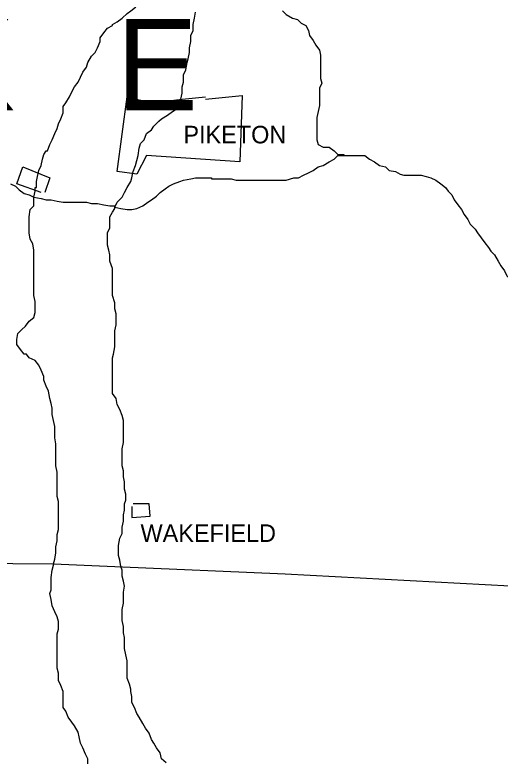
# Model space of a CAD drawing. Extents: x 0 to 34, y 0 to 22.
# Drawn here: x 5.85 to 6.39, y 17.259 to 18.089 of the extents above; entities that cross this region are included whole.
import ezdxf

# ---------------------------------------------------------------- set-up
doc = ezdxf.new("R2010")
doc.units = 0
doc.layers.add('Default', color=7, linetype='Continuous')
doc.layers.add('TR_Turning_Path1', color=7, linetype='Continuous')

msp = doc.modelspace()

# ---------------------------------------------------------------- linework, layer by layer
at = {"layer": 'Default'}
for points in [[(5.95854, 18.07894), (5.96399, 18.08167), (5.96944, 18.08576), (5.9749, 18.09121), (5.97899, 18.09394), (5.98444, 18.09803), (5.98717, 18.10212), (5.98853, 18.10894), (5.99262, 18.11575), (5.99399, 18.11712)], [(6.04443, 18.05304), (6.0458, 18.05985), (6.0458, 18.06667), (6.04852, 18.07212), (6.04852, 18.07894), (6.04989, 18.08576), (6.05125, 18.09257)], [(6.14805, 18.09394), (6.15214, 18.08985), (6.15896, 18.08576), (6.16441, 18.08439), (6.1685, 18.0803), (6.17396, 18.07758), (6.17668, 18.07212), (6.17805, 18.06667), (6.18214, 18.06122), (6.18487, 18.05576), (6.18896, 18.05031), (6.19032, 18.04486), (6.19032, 18.03804), (6.19032, 18.03122), (6.19032, 18.02577), (6.19032, 18.01895), (6.19168, 18.0135)], [(5.88628, 17.93851), (5.889, 17.94533), (5.89173, 17.95078), (5.89446, 17.9576), (5.89718, 17.96305), (5.89855, 17.9685), (5.90127, 17.97396), (5.904, 17.98077), (5.904, 17.98759), (5.90673, 17.99168), (5.91082, 17.9985), (5.91354, 18.00395), (5.91627, 18.00941), (5.92036, 18.01486), (5.92309, 18.02031), (5.92582, 18.02577), (5.92991, 18.03122), (5.93127, 18.03667), (5.93536, 18.04349), (5.93945, 18.04758), (5.94218, 18.05304), (5.9449, 18.05985), (5.9449, 18.06394), (5.94899, 18.0694), (5.95308, 18.07485), (5.95854, 18.07758), (5.95854, 18.07894)], [(5.96126, 17.87579), (5.96399, 17.88124), (5.96944, 17.8867), (5.97217, 17.89215), (5.9749, 17.89761), (5.97899, 17.90442), (5.98035, 17.90851), (5.98172, 17.91533), (5.98444, 17.92215), (5.98581, 17.9276), (5.98717, 17.93305), (5.98853, 17.94124), (5.9899, 17.94669), (5.99399, 17.95078), (5.99671, 17.9576), (6.00217, 17.96169), (6.00489, 17.96578), (6.01035, 17.97123), (6.01307, 17.97396), (6.01989, 17.97805), (6.02534, 17.98214), (6.02944, 17.98486), (6.03353, 17.99032), (6.03489, 17.99577), (6.03625, 18.00259), (6.03625, 18.00941), (6.03762, 18.01486), (6.03762, 18.02304), (6.04034, 18.02849), (6.04171, 18.03667), (6.04307, 18.04076), (6.04443, 18.04758), (6.04443, 18.05167), (6.04443, 18.05304)], [(6.19168, 18.0135), (6.18896, 18.00804), (6.18896, 18.00259), (6.18896, 17.99577), (6.18896, 17.98895), (6.18759, 17.98214), (6.18623, 17.97532), (6.18623, 17.96987), (6.18623, 17.96305), (6.18623, 17.9576), (6.18623, 17.95078), (6.18759, 17.94533), (6.19305, 17.9426), (6.19986, 17.9426), (6.20532, 17.93851), (6.20941, 17.93442), (6.21622, 17.93442), (6.21622, 17.93305)], [(6.06216, 17.99577), (6.10306, 17.99986), (6.10033, 17.92624), (5.99671, 17.93305), (5.98581, 17.9126), (5.96399, 17.91533), (5.9749, 17.9985), (6.00217, 17.99168), (6.03625, 17.99577), (6.06216, 17.9985)], [(5.87401, 17.89761), (5.87401, 17.90442), (5.87537, 17.90988), (5.87673, 17.91669), (5.87946, 17.92215), (5.88082, 17.92896), (5.88219, 17.93442), (5.88491, 17.93851), (5.88628, 17.93851)], [(6.06897, 17.90715), (6.07579, 17.90715), (6.08397, 17.90715), (6.09079, 17.90715), (6.09624, 17.90579), (6.10306, 17.90579), (6.10988, 17.90579), (6.11669, 17.90579), (6.12215, 17.90579), (6.1276, 17.90579), (6.13578, 17.90579), (6.14124, 17.90579), (6.14805, 17.90579), (6.15214, 17.90579), (6.16032, 17.90851), (6.16578, 17.90851), (6.17123, 17.91124), (6.17668, 17.91397), (6.18214, 17.91669), (6.18759, 17.92078), (6.19305, 17.92215), (6.19986, 17.92624), (6.20532, 17.92896), (6.20941, 17.93305), (6.21486, 17.93305), (6.21622, 17.93305)], [(6.06897, 17.90715), (6.07579, 17.90715), (6.08397, 17.90715), (6.09079, 17.90715), (6.09624, 17.90579), (6.10306, 17.90579), (6.10988, 17.90579), (6.11669, 17.90579), (6.12215, 17.90579), (6.1276, 17.90579), (6.13578, 17.90579), (6.14124, 17.90579), (6.14805, 17.90579), (6.15214, 17.90579), (6.16032, 17.90851), (6.16578, 17.90851), (6.17123, 17.91124), (6.17668, 17.91397), (6.18214, 17.91669), (6.18759, 17.92078), (6.19305, 17.92215), (6.19986, 17.92624), (6.20532, 17.92896), (6.20941, 17.93305), (6.21486, 17.93305), (6.21622, 17.93305)], [(6.21622, 17.93305), (6.22304, 17.93305), (6.22849, 17.93305), (6.23395, 17.93305), (6.2394, 17.93305), (6.24486, 17.92896), (6.25031, 17.92624), (6.25576, 17.92215), (6.26258, 17.92078), (6.26667, 17.91669), (6.27349, 17.91533), (6.27894, 17.9126), (6.28303, 17.91124), (6.28985, 17.91124), (6.29667, 17.91124), (6.30212, 17.91124), (6.30757, 17.90988), (6.31303, 17.90851), (6.31848, 17.90579), (6.31848, 17.90579)], [(6.21622, 17.93305), (6.22304, 17.93305), (6.22849, 17.93305), (6.23395, 17.93305), (6.2394, 17.93305), (6.24486, 17.92896), (6.25031, 17.92624), (6.25576, 17.92215), (6.26258, 17.92078), (6.26667, 17.91669), (6.27349, 17.91533), (6.27894, 17.9126), (6.28303, 17.91124), (6.28985, 17.91124), (6.29667, 17.91124), (6.30212, 17.91124), (6.30757, 17.90988), (6.31303, 17.90851), (6.31848, 17.90579), (6.31848, 17.90579)], [(5.87946, 17.89215), (5.85219, 17.9017), (5.85901, 17.92078), (5.889, 17.90851), (5.88355, 17.89215)], [(5.96126, 17.87579), (5.96808, 17.87443), (5.9749, 17.87306), (5.98035, 17.87306), (5.98581, 17.87443), (5.99262, 17.87715), (5.99808, 17.88124), (6.00217, 17.88397), (6.00762, 17.88806), (6.01171, 17.89215), (6.01716, 17.89624), (6.02125, 17.89897), (6.02671, 17.9017), (6.03353, 17.90442), (6.03762, 17.90579), (6.0458, 17.90715), (6.05125, 17.90851), (6.05807, 17.90851), (6.06352, 17.90851), (6.06897, 17.90851), (6.06897, 17.90715)], [(5.96126, 17.87579), (5.96808, 17.87443), (5.9749, 17.87306), (5.98035, 17.87306), (5.98581, 17.87443), (5.99262, 17.87715), (5.99808, 17.88124), (6.00217, 17.88397), (6.00762, 17.88806), (6.01171, 17.89215), (6.01716, 17.89624), (6.02125, 17.89897), (6.02671, 17.9017), (6.03353, 17.90442), (6.03762, 17.90579), (6.0458, 17.90715), (6.05125, 17.90851), (6.05807, 17.90851), (6.06352, 17.90851), (6.06897, 17.90851), (6.06897, 17.90715)], [(5.84537, 17.9017), (5.85083, 17.89897), (5.85492, 17.89488), (5.86037, 17.89079), (5.86582, 17.88943), (5.87128, 17.8867), (5.87128, 17.8867), (5.87128, 17.8867)], [(5.84537, 17.9017), (5.85083, 17.89897), (5.85492, 17.89488), (5.86037, 17.89079), (5.86582, 17.88943), (5.87128, 17.8867), (5.87128, 17.8867), (5.87128, 17.8867)], [(6.31848, 17.90579), (6.32393, 17.9017), (6.32939, 17.89761), (6.33211, 17.89352), (6.3362, 17.88943), (6.33893, 17.88397), (6.34302, 17.87852), (6.34711, 17.87306), (6.34984, 17.86761), (6.35393, 17.86216), (6.35666, 17.8567), (6.36211, 17.85125), (6.36484, 17.84716), (6.36893, 17.84171), (6.37302, 17.83625), (6.37711, 17.8308), (6.37983, 17.82671), (6.38392, 17.82262), (6.38392, 17.82262)], [(6.31848, 17.90579), (6.32393, 17.9017), (6.32939, 17.89761), (6.33211, 17.89352), (6.3362, 17.88943), (6.33893, 17.88397), (6.34302, 17.87852), (6.34711, 17.87306), (6.34984, 17.86761), (6.35393, 17.86216), (6.35666, 17.8567), (6.36211, 17.85125), (6.36484, 17.84716), (6.36893, 17.84171), (6.37302, 17.83625), (6.37711, 17.8308), (6.37983, 17.82671), (6.38392, 17.82262), (6.38392, 17.82262)], [(5.87128, 17.8867), (5.87264, 17.89352), (5.87264, 17.89761), (5.87401, 17.89761)], [(5.86037, 17.71218), (5.85628, 17.71763), (5.85219, 17.72309), (5.85219, 17.72854), (5.85355, 17.73536), (5.85764, 17.73945), (5.86173, 17.74354), (5.86582, 17.74899), (5.87128, 17.75308), (5.87264, 17.75854), (5.87264, 17.76399), (5.87264, 17.77081), (5.87128, 17.77762), (5.87128, 17.78444), (5.87128, 17.79126), (5.87128, 17.79671), (5.87128, 17.80353), (5.87128, 17.80898), (5.87128, 17.8158), (5.87128, 17.82262), (5.87128, 17.82807), (5.86991, 17.83489), (5.86719, 17.84034), (5.86582, 17.84716), (5.86582, 17.85261), (5.86582, 17.85943), (5.86582, 17.86488), (5.86719, 17.87306), (5.87128, 17.87715), (5.87128, 17.88397), (5.87128, 17.88533), (5.87128, 17.8867)], [(5.87128, 17.8867), (5.87946, 17.88533), (5.88491, 17.88397), (5.89037, 17.88397), (5.89718, 17.88261), (5.904, 17.88124), (5.90945, 17.88124), (5.91627, 17.88124), (5.92309, 17.88124), (5.92991, 17.88124), (5.93536, 17.87988), (5.94218, 17.87988), (5.94899, 17.87852), (5.95581, 17.87715), (5.96126, 17.87715), (5.96126, 17.87579)], [(5.87128, 17.8867), (5.87946, 17.88533), (5.88491, 17.88397), (5.89037, 17.88397), (5.89718, 17.88261), (5.904, 17.88124), (5.90945, 17.88124), (5.91627, 17.88124), (5.92309, 17.88124), (5.92991, 17.88124), (5.93536, 17.87988), (5.94218, 17.87988), (5.94899, 17.87852), (5.95581, 17.87715), (5.96126, 17.87715), (5.96126, 17.87579)], [(5.96126, 17.73263), (5.96126, 17.73809), (5.96263, 17.7449), (5.96263, 17.75172), (5.96263, 17.75717), (5.96126, 17.76263), (5.96126, 17.76944), (5.95854, 17.77762), (5.95854, 17.78308), (5.95854, 17.7899), (5.95854, 17.79535), (5.95854, 17.80217), (5.95854, 17.80762), (5.95581, 17.8158), (5.95581, 17.82262), (5.95445, 17.82807), (5.95308, 17.83352), (5.95308, 17.84034), (5.95308, 17.84716), (5.95581, 17.85261), (5.95581, 17.85943), (5.95581, 17.86488), (5.95854, 17.87034), (5.96126, 17.87443), (5.96126, 17.87579)], [(6.38392, 17.82262), (6.38801, 17.8158), (6.39074, 17.81035), (6.39483, 17.80489), (6.39756, 17.79944), (6.40301, 17.79399), (6.40574, 17.7899), (6.40983, 17.78581), (6.41392, 17.77899), (6.41801, 17.7749), (6.4221, 17.76944), (6.42892, 17.76672), (6.43437, 17.76399), (6.43982, 17.76263), (6.44664, 17.76126), (6.4521, 17.76126), (6.45891, 17.7599), (6.46573, 17.75854), (6.47118, 17.75854), (6.478, 17.75854), (6.47936, 17.75854)], [(6.38392, 17.82262), (6.38801, 17.8158), (6.39074, 17.81035), (6.39483, 17.80489), (6.39756, 17.79944), (6.40301, 17.79399), (6.40574, 17.7899), (6.40983, 17.78581), (6.41392, 17.77899), (6.41801, 17.7749), (6.4221, 17.76944), (6.42892, 17.76672), (6.43437, 17.76399), (6.43982, 17.76263), (6.44664, 17.76126), (6.4521, 17.76126), (6.45891, 17.7599), (6.46573, 17.75854), (6.47118, 17.75854), (6.478, 17.75854), (6.47936, 17.75854)], [(5.96808, 17.47631), (5.96672, 17.48313), (5.96535, 17.48858), (5.96535, 17.4954), (5.96535, 17.49949), (5.96672, 17.50767), (5.96944, 17.51312), (5.96944, 17.51994), (5.97081, 17.52676), (5.97081, 17.53357), (5.97217, 17.53903), (5.97217, 17.54584), (5.97353, 17.54993), (5.97353, 17.55675), (5.97217, 17.5622), (5.97217, 17.57038), (5.97081, 17.57584), (5.97081, 17.58266), (5.96944, 17.58811), (5.96944, 17.59493), (5.96944, 17.60174), (5.96944, 17.6072), (5.97081, 17.61401), (5.97081, 17.61947), (5.97081, 17.62628), (5.97081, 17.63174), (5.97081, 17.63856), (5.96944, 17.64401), (5.96672, 17.65083), (5.96399, 17.65628), (5.96263, 17.6631), (5.95854, 17.66855), (5.95854, 17.67537), (5.95854, 17.68082), (5.95854, 17.68764), (5.95854, 17.69446), (5.95854, 17.70127), (5.95854, 17.70809), (5.9599, 17.71218), (5.96126, 17.72036), (5.96126, 17.72581), (5.96126, 17.73127), (5.96126, 17.73127), (5.96126, 17.73263)], [(5.89309, 17.47904), (5.89446, 17.48449), (5.89582, 17.49131), (5.89582, 17.49812), (5.89718, 17.50494), (5.89718, 17.51176), (5.89855, 17.51721), (5.89855, 17.52266), (5.89855, 17.53085), (5.89855, 17.5363), (5.89855, 17.54175), (5.89855, 17.54857), (5.89718, 17.55402), (5.89718, 17.5622), (5.89718, 17.56766), (5.89718, 17.57447), (5.89718, 17.58129), (5.89582, 17.58811), (5.89582, 17.59356), (5.89582, 17.59902), (5.89582, 17.60583), (5.89582, 17.61265), (5.89446, 17.61947), (5.89446, 17.62628), (5.89446, 17.63174), (5.89309, 17.63856), (5.89173, 17.64537), (5.89173, 17.65219), (5.89037, 17.65764), (5.889, 17.6631), (5.88764, 17.67128), (5.88491, 17.67673), (5.88219, 17.68355), (5.88219, 17.68764), (5.87946, 17.69446), (5.87673, 17.69991), (5.87264, 17.70536), (5.86582, 17.70809), (5.8631, 17.71218), (5.86173, 17.71218), (5.86037, 17.71218)], [(5.98035, 17.54312), (5.98035, 17.53085), (6.0008, 17.53221), (5.99944, 17.54584), (5.98172, 17.54584)], [(5.30546, 17.4954), (5.44725, 17.48858), (5.56996, 17.48449), (5.75675, 17.4804), (5.89309, 17.47904), (5.96126, 17.47631), (6.15078, 17.46813), (6.42892, 17.45313), (6.53935, 17.44631), (6.69887, 17.43541), (6.73296, 17.43268)], [(5.904, 17.32497), (5.904, 17.33179), (5.904, 17.33724), (5.90127, 17.34406), (5.89855, 17.34951), (5.89855, 17.35769), (5.89718, 17.36314), (5.89718, 17.36996), (5.89718, 17.37678), (5.89718, 17.38223), (5.89718, 17.38905), (5.89718, 17.3945), (5.89718, 17.40132), (5.89855, 17.40677), (5.89855, 17.41495), (5.89718, 17.42041), (5.89446, 17.42586), (5.89173, 17.43268), (5.89037, 17.4395), (5.889, 17.44631), (5.89037, 17.4504), (5.89037, 17.45722), (5.89037, 17.46404), (5.89173, 17.47222), (5.89309, 17.47767), (5.89309, 17.47904)], [(5.97899, 17.33997), (5.97763, 17.34542), (5.9749, 17.35224), (5.9749, 17.35769), (5.9749, 17.36587), (5.9749, 17.37133), (5.97353, 17.37814), (5.97217, 17.38496), (5.97217, 17.39041), (5.97217, 17.39723), (5.97081, 17.40268), (5.97081, 17.4095), (5.96944, 17.41632), (5.96944, 17.42314), (5.96944, 17.42859), (5.97081, 17.43541), (5.97081, 17.44086), (5.97081, 17.44768), (5.97217, 17.45449), (5.97081, 17.45995), (5.96944, 17.4654), (5.96944, 17.47222), (5.96808, 17.47631), (5.96808, 17.47631)], [(6.01853, 17.25816), (6.01307, 17.26225), (6.01171, 17.26907), (6.00762, 17.27452), (6.00489, 17.27998), (6.00217, 17.28407), (5.99944, 17.29088), (5.99535, 17.29634), (5.99262, 17.30179), (5.98853, 17.30861), (5.98581, 17.3127), (5.98308, 17.31952), (5.98035, 17.32497), (5.98035, 17.33179), (5.97899, 17.33724), (5.97899, 17.3386), (5.97899, 17.33997)], [(5.93127, 17.2568), (5.93127, 17.26225), (5.92854, 17.26771), (5.92582, 17.27452), (5.92309, 17.27998), (5.92172, 17.28679), (5.92036, 17.29225), (5.91627, 17.29906), (5.91354, 17.30315), (5.90945, 17.30861), (5.90673, 17.31542), (5.904, 17.31952), (5.904, 17.32497), (5.904, 17.32497)]]:
    msp.add_lwpolyline(points, dxfattribs=at)

# ---------------------------------------------------------------- texts
for s, p in [('PIKETON', (6.03762, 17.94669)), ('WAKEFIELD', (5.9899, 17.50358))]:
    msp.add_text(s, height=0.019502, dxfattribs=at).set_placement(p)
at = {"layer": 'TR_Turning_Path1'}
msp.add_text('P   I   K   E', height=0.1014887, dxfattribs=at).set_placement((5.40499, 17.9835))

doc.saveas('drawing.dxf')
